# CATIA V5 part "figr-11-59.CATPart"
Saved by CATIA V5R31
Part number: Part1
Bounding box of the stored display mesh (mm): x -59.829 to 59.829, y -71.429 to 72.174, z -61 to 76
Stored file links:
  D:\PROJECTS\Project 2021\US EDITION\CATIA V5 6R 2021\Resources\Part Files\c11_catia_v5_6r2021_prt\figr-11-59.CATPart
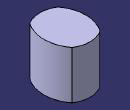
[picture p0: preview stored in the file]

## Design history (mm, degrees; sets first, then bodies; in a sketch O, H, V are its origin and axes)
Set1
  Extrude1: Element1 Sketch1, Lim1 76, Lim2 61, Direction xy-plane
Body1 (main body)
  Sketch1 on xy-plane, origin (0, 0, 0), H (0, 1, 0), V (-1, 0, 0)
    arc A1 centre (0, -40) radius 100 from (-60, 40) to (60, 40) cw
    point P2 (0, 60)
    point P3 (-60, 40)
    point P4 (60, 40)
    axis line L1 (-90, 0) -> (80, 0)
    point P6 (80, 0)
    point P7 (60, -40)
    point P8 (-60, -40)
    arc A2 centre (0, 40) radius 100 from (-60, -40) to (60, -40) ccw
    arc A3 centre (4.2857, 0) radius 75.7143 from (-60, 40) to (-60, -40) ccw
    arc A4 centre (0.3727, 0) radius 71.8012 from (60, -40) to (60, 40) ccw
    coincidence: A1 P2, P2 V, A3 P6
    horizontal: L1 H
    symmetry: P4 P7 L1, P3 P8 L1, A1 A2 L1
    tangency: A4 A3
  Sketch2 on xy-plane, origin (0, 0, 0), H (1, 0, 0), V (0, 1, 0)
    spline S1 through (80, 90) (60, 60) (70, 0) (50, -50) (50, -80)
    point P1 (70, 0)
    coincidence: P1 H
  CloseSurface1: CloseElement Extrude1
